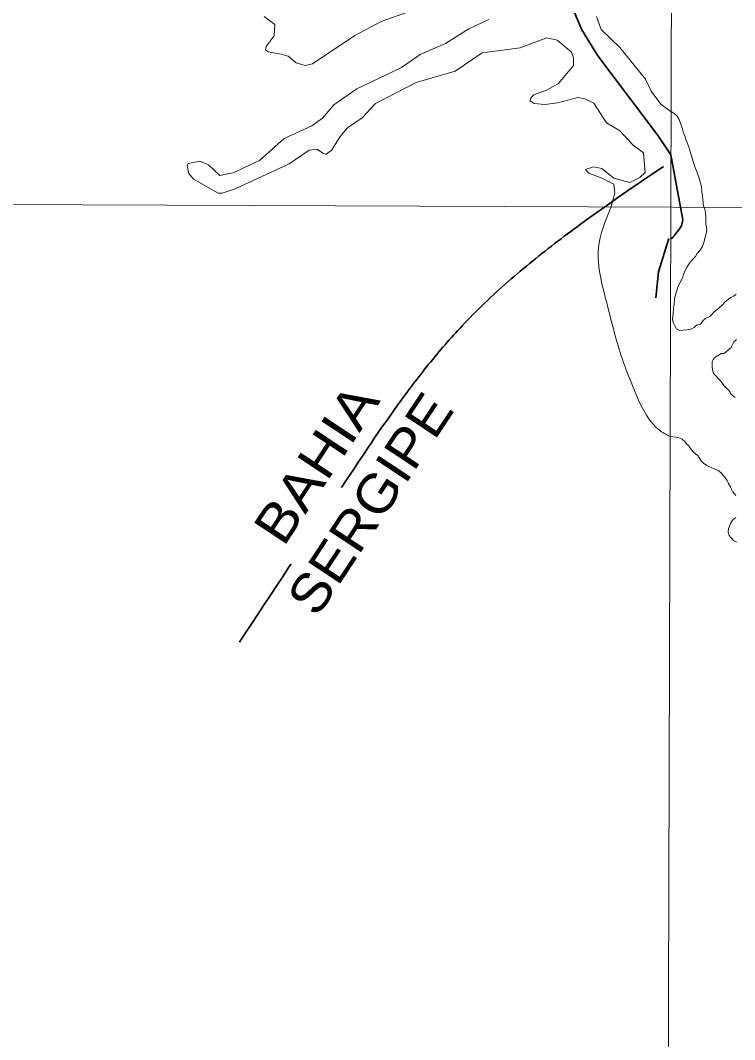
# Model space of a CAD drawing. Extents: x 553962 to 842807, y 8883888 to 9032388.
# Drawn here: x 584255 to 585748, y 8908229 to 8910360 of the extents above; entities that cross this region are included whole.
import ezdxf
from ezdxf.enums import TextEntityAlignment as Align

# ---------------------------------------------------------------- set-up
doc = ezdxf.new("R2010")
doc.units = 0
doc.header["$LTSCALE"] = 160
doc.linetypes.add('LONG_DASH_SHORT_DASH', pattern=[9.9, 6, -1.2, 1.5, -1.2])
doc.layers.add('6', color=7, linetype='Continuous', lineweight=13)

msp = doc.modelspace()

# ---------------------------------------------------------------- linework, layer by layer
at = {"layer": '6'}
msp.add_line((576954.3, 8910001), (623612.7, 8909833), dxfattribs=at)
for points in [[(585656.3, 8924738.8), (585614.8, 8909969.8), (585579.9, 8898162.7)], [(585234.4, 8910361.7), (585192.5, 8910342.6), (585144.1, 8910312.1), (585090.8, 8910289), (585052.1, 8910261.8), (584958.3, 8910216.9), (584910.5, 8910183.5), (584886.5, 8910155.6), (584864.3, 8910139.8), (584806.9, 8910113.4), (584754.7, 8910067.2), (584700, 8910041.6), (584672.2, 8910035.9), (584648.3, 8910057.9), (584630.4, 8910065.7), (584605.9, 8910061), (584603.9, 8910056.1)], [(584764.8, 8910368.3), (584787.4, 8910351.4), (584785.9, 8910327.6), (584769.2, 8910305.8), (584767.6, 8910298.8), (584772.9, 8910294.4), (584800, 8910289.5), (584814.7, 8910285.1), (584831.6, 8910271.7), (584850.3, 8910265.6), (584865.5, 8910269.3), (584954.5, 8910328.5), (585009.6, 8910357.9), (585064.1, 8910377.6)], [(585613, 8910170.9), (585594.1, 8910185.2), (585574.1, 8910212), (585562.3, 8910236.9), (585508.4, 8910303.8), (585469.5, 8910341.1), (585459.3, 8910368.4)], [(584603.9, 8910056.1), (584607.2, 8910039.8), (584616.9, 8910028.5), (584628.5, 8910021.9), (584668.8, 8909998.9), (584676.7, 8909998.9), (584704, 8910007.6), (584817.2, 8910060.3), (584858.8, 8910088.5), (584875.1, 8910090.6), (584888.6, 8910081.7), (584893.5, 8910080.6), (584905.8, 8910088), (584923.7, 8910117.4), (584939.2, 8910135.5), (584969.7, 8910156.6), (584997.7, 8910186.3), (585082.5, 8910230.4), (585164.2, 8910254), (585220.6, 8910292.1), (585299.9, 8910302.5), (585355.9, 8910323.7), (585377.1, 8910318.9), (585407.1, 8910293.7), (585411.8, 8910281.8), (585411.3, 8910265.8), (585380.1, 8910228.3), (585354.8, 8910214.1), (585328.7, 8910204.3), (585323, 8910199), (585320.6, 8910192.2), (585329.2, 8910186.2), (585351.9, 8910184.5), (585378.8, 8910187.8), (585420.4, 8910199.1), (585435, 8910196.4)], [(585435, 8910196.4), (585454.1, 8910186.9), (585480.4, 8910146.2), (585507.6, 8910130.2), (585536, 8910099.4), (585557.7, 8910083.3), (585561.6, 8910042.2), (585550.1, 8910031.9), (585529.2, 8910021.5), (585495.8, 8910030.1), (585470.4, 8910050.8), (585453.4, 8910054.2), (585436.7, 8910048.7), (585443.6, 8910040.4), (585470.9, 8910030.2), (585495.8, 8910018), (585497.8, 8909999), (585489.3, 8909969)], [(585620.4, 8909758.5), (585621.7, 8909767), (585622.4, 8909778.7), (585626.9, 8909793), (585629.5, 8909802.2), (585634.1, 8909811.3), (585639.3, 8909821), (585640.6, 8909826.9), (585645.2, 8909837.3), (585649.1, 8909845.1), (585655.6, 8909854.9), (585662.1, 8909862.1), (585666.7, 8909866.6), (585669.9, 8909872.5), (585675.8, 8909879), (585681, 8909887.4), (585684.9, 8909897.8), (585686.2, 8909905), (585688.8, 8909914.1), (585690.1, 8909923.2), (585688, 8909935.1), (585688.1, 8909940.1), (585688.1, 8909944.1), (585688.2, 8909950.1), (585687.7, 8909956.1), (585686.8, 8909963.1), (585685.3, 8909967.1), (585683.7, 8909969.3)], [(585751.4, 8909787.4), (585747.4, 8909784.4), (585740.4, 8909781), (585736.4, 8909778), (585727.9, 8909770.9), (585727.9, 8909770.9), (585721.4, 8909763.7), (585721.4, 8909763.7), (585711.6, 8909755.9), (585705.8, 8909750.7), (585705.8, 8909750.7), (585700.5, 8909745.5), (585696.6, 8909740.9), (585687.5, 8909737), (585682.3, 8909732.5), (585677.1, 8909725.3), (585668.6, 8909722.7), (585664.1, 8909718.2), (585656.9, 8909714.2), (585648.4, 8909712.9), (585640.3, 8909712.6), (585632.8, 8909711.7), (585632.8, 8909711.7), (585626.9, 8909714.9), (585623.7, 8909720.1), (585623.7, 8909720.1), (585619.8, 8909728.6), (585618.5, 8909735.1), (585619.8, 8909746.2), (585620.4, 8909758.5)], [(585749.6, 8909571.7), (585743.7, 8909575.7), (585739.7, 8909580.2), (585738.2, 8909584.3), (585734.3, 8909588.3), (585730.3, 8909592.8), (585725.8, 8909596.9), (585721.9, 8909602.9), (585718.4, 8909606.9), (585714.9, 8909610.9), (585708.5, 8909617.5), (585704.5, 8909621.5), (585703, 8909626.6), (585701.6, 8909634.6), (585701.2, 8909642.1), (585701.2, 8909646.6), (585703.2, 8909651.1), (585706.8, 8909655.6), (585712.8, 8909659), (585720.3, 8909663.5), (585725.8, 8909663.4), (585730.4, 8909667.4), (585735.4, 8909671.4), (585740.9, 8909676.4), (585743.5, 8909681.4), (585747, 8909688.3), (585752.1, 8909692.8)], [(585613.4, 8909490.1), (585625.1, 8909488.8), (585632, 8909487.3), (585638.9, 8909484.6), (585645, 8909479.2), (585648.1, 8909474.3), (585652.7, 8909470.4), (585655.8, 8909465.1), (585655.8, 8909465.1), (585661.5, 8909458.2), (585661.5, 8909458.2), (585665.7, 8909454.3), (585670.5, 8909450.3), (585674, 8909446.2), (585678.4, 8909439.2), (585683.4, 8909434.7), (585690.2, 8909429.4), (585690.2, 8909429.4), (585700.8, 8909424.5), (585707.3, 8909422), (585715.3, 8909418.4), (585721.7, 8909412.9), (585724.7, 8909408.8), (585728.2, 8909404.8), (585733.1, 8909397.8), (585735.6, 8909391.8), (585739.5, 8909385.2), (585741, 8909381.2), (585744.5, 8909374.2), (585750.9, 8909366.6)], [(585750.6, 8909320.6), (585744, 8909315.1), (585740, 8909308.1), (585738.2, 8909303.8), (585735.8, 8909297.5), (585735.1, 8909290.1), (585736.9, 8909283.3), (585740.3, 8909278.6), (585745.7, 8909272.5), (585752.7, 8909269.5)]]:
    msp.add_lwpolyline(points, dxfattribs=at)
at = {"layer": '6', "linetype": 'LONG_DASH_SHORT_DASH', "lineweight": 35}
for points in [[(585403.7, 8910399.5), (585428.8, 8910340.2), (585462.1, 8910286.2), (585588.3, 8910118.5), (585615.1, 8910078.7)], [(585615.1, 8910078.7), (585640.3, 8909942.8), (585637.2, 8909930.8), (585631.7, 8909922.3), (585625.6, 8909914.8), (585619, 8909906.4), (585614.6, 8909902.8)], [(585583.7, 8909780.1), (585589.5, 8909834.4), (585611.1, 8909903.9)]]:
    msp.add_lwpolyline(points, dxfattribs=at)
at = {"layer": '6'}
for points in [[(585683.7, 8909969.3), (585680.5, 8909997.4), (585678.2, 8910014.6), (585665.5, 8910053.6), (585654.1, 8910090.4), (585639.2, 8910132.8), (585625.4, 8910162.7), (585613, 8910170.9)], [(585489.3, 8909969), (585463.9, 8909884.3), (585482.4, 8909764.2), (585502.7, 8909686.5), (585543.4, 8909575.6), (585593.3, 8909501.7), (585613.4, 8909490.1)]]:
    msp.add_spline(points, degree=3, dxfattribs=at)
at = {"layer": '6', "linetype": 'LONG_DASH_SHORT_DASH', "lineweight": 35}
msp.add_spline([(585599.5, 8910054.8), (585178.8, 8909721.7), (584922.2, 8909376.8), (584712.9, 8909059.8)], degree=3, dxfattribs=at)

# ---------------------------------------------------------------- texts
at = {"layer": '6'}
for s, width, p in [('BAHIA', 1.15, (584907.2, 8909411.3)), ('SERGIPE', 1.1, (585019.6, 8909327.4))]:
    msp.add_text(s, height=80, rotation=56.48, dxfattribs=dict(at, width=width)).set_placement(p, align=Align.CENTER)

doc.saveas('drawing.dxf')
